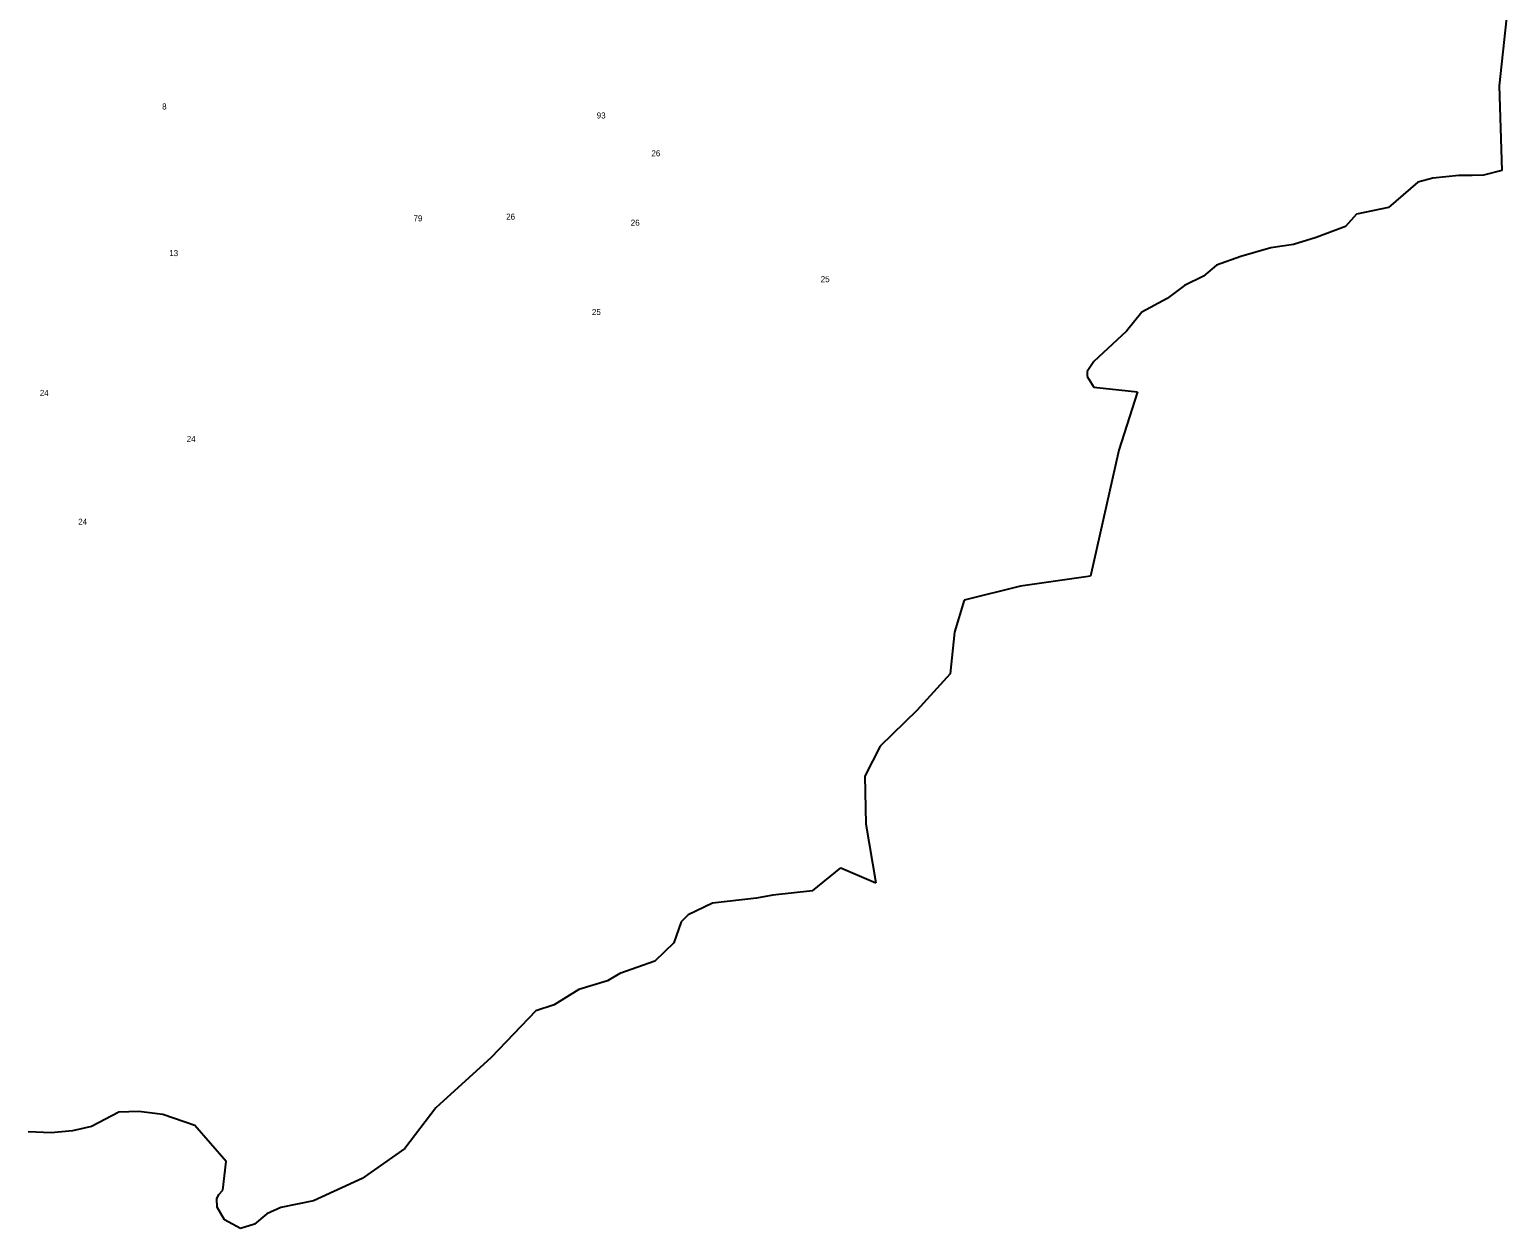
# Model space of a CAD drawing. Extents: x -772472 to -767535, y -969581 to -965387.
# Drawn here: x -770002 to -767535, y -969496 to -967499 of the extents above; entities that cross this region are included whole.
import ezdxf

# ---------------------------------------------------------------- set-up
doc = ezdxf.new("R2010")
doc.units = 0
doc.layers.add('Vrstva 13', color=7, linetype='Continuous')
doc.layers.add('Vrstva 24', color=7, linetype='Continuous')

msp = doc.modelspace()

# ---------------------------------------------------------------- linework, layer by layer
at = {"layer": 'Vrstva 13'}
for p, q in [((-767534.62, -967420.5), (-767553.38, -967593.03)), ((-767553.38, -967593.03), (-767548.64, -967734.13)), ((-767620.41, -967742.16), (-767663.81, -967746.68)), ((-767598.25, -967742.16), (-767620.41, -967742.16)), ((-767579.27, -967741.71), (-767598.25, -967742.16)), ((-767548.64, -967734.13), (-767579.27, -967741.71)), ((-767688.67, -967753.47), (-767737.5, -967795.53)), ((-767663.81, -967746.68), (-767688.67, -967753.47)), ((-767790.85, -967806.38), (-767809.38, -967827.19)), ((-767737.5, -967795.53), (-767790.85, -967806.38)), ((-767809.38, -967827.19), (-767858.21, -967845.73)), ((-767933.71, -967862.47), (-767983.89, -967876.94)), ((-767896.18, -967857.04), (-767933.71, -967862.47)), ((-767858.21, -967845.73), (-767896.18, -967857.04)), ((-767983.89, -967876.94), (-768024.14, -967891.42)), ((-768045.84, -967909.96), (-768077.49, -967925.34)), ((-768024.14, -967891.42), (-768045.84, -967909.96)), ((-768077.49, -967925.34), (-768106.42, -967947.05)), ((-768106.42, -967947.05), (-768148.92, -967969.66)), ((-768148.92, -967969.66), (-768174.23, -968001.32)), ((-768174.23, -968001.32), (-768228.94, -968051.97)), ((-768228.94, -968051.97), (-768239.78, -968068.71)), ((-768239.78, -968068.71), (-768239.78, -968077.3)), ((-768239.78, -968077.3), (-768228.48, -968094.94)), ((-768228.48, -968094.94), (-768156.15, -968102.63)), ((-768156.15, -968102.63), (-768186.89, -968199.87)), ((-768186.89, -968199.87), (-768234.14, -968409.95)), ((-768350.78, -968426.23), (-768444.81, -968449.75)), ((-768234.14, -968409.95), (-768350.78, -968426.23)), ((-768444.81, -968449.75), (-768461.09, -968503.12)), ((-768461.09, -968503.12), (-768468.31, -968572.76)), ((-768468.31, -968572.76), (-768523.47, -968633.37)), ((-768523.47, -968633.37), (-768584.95, -968693.07)), ((-768584.95, -968693.07), (-768610.27, -968742.82)), ((-768610.27, -968742.82), (-768608.46, -968822.42)), ((-768608.46, -968822.42), (-768592.06, -968920.87)), ((-768697.4, -968933.99), (-768650.16, -968895.77)), ((-768650.16, -968895.77), (-768592.06, -968920.87)), ((-768790.87, -968946.08), (-768864.11, -968954.67)), ((-768763.3, -968941.1), (-768790.87, -968946.08)), ((-768697.4, -968933.99), (-768763.3, -968941.1)), ((-768904.35, -968974.12), (-768916.11, -968985.88)), ((-768864.11, -968954.67), (-768904.35, -968974.12)), ((-768916.11, -968985.88), (-768928.76, -969020.7)), ((-768928.76, -969020.7), (-768960.41, -969051.01)), ((-769018.74, -969071.81), (-769039.08, -969084.02)), ((-768960.41, -969051.01), (-769018.74, -969071.81)), ((-769086.55, -969098.49), (-769128.14, -969123.82)), ((-769039.08, -969084.02), (-769086.55, -969098.49)), ((-769128.14, -969123.82), (-769158.43, -969133.77)), ((-769158.43, -969133.77), (-769233.03, -969212.02)), ((-769233.03, -969212.02), (-769325.26, -969295.69)), ((-769325.26, -969295.69), (-769376.8, -969363.53)), ((-769853.3, -969302.92), (-769898.96, -969326.89)), ((-769819.84, -969302.01), (-769853.3, -969302.92)), ((-769780.06, -969306.54), (-769819.84, -969302.01)), ((-769726.72, -969325.08), (-769780.06, -969306.54)), ((-769965.87, -969337.29), (-770004.3, -969335.48)), ((-769930.61, -969334.13), (-769965.87, -969337.29)), ((-769898.96, -969326.89), (-769930.61, -969334.13)), ((-769674.28, -969385.23), (-769726.72, -969325.08)), ((-769376.8, -969363.53), (-769447.77, -969413.28)), ((-769679.7, -969432.72), (-769674.28, -969385.23)), ((-769447.77, -969413.28), (-769528.7, -969450.82)), ((-769690.1, -969447.19), (-769686.48, -969439.96)), ((-769686.48, -969439.96), (-769679.7, -969432.72)), ((-769689.19, -969461.21), (-769690.1, -969447.19)), ((-769676.99, -969482.02), (-769689.19, -969461.21)), ((-769583.4, -969461.66), (-769606.46, -969472.52)), ((-769528.7, -969450.82), (-769583.4, -969461.66)), ((-769650.31, -969496.49), (-769676.99, -969482.02)), ((-769627.26, -969489.25), (-769650.31, -969496.49)), ((-769606.46, -969472.52), (-769627.26, -969489.25))]:
    msp.add_line(p, q, dxfattribs=at)

# ---------------------------------------------------------------- texts
at = {"layer": 'Vrstva 24'}
for s, p in [('8', (-769781.046, -967632.22)), ('93', (-769056.99, -967647.17)), ('26', (-768965.93, -967710.2)), ('79', (-769362.318, -967818.54)), ('26', (-769207.87, -967815.7)), ('26', (-769000.33, -967825.86)), ('13', (-769769.271, -967876.53)), ('25', (-768683.746, -967919.94)), ('25', (-769064.986, -967974.66)), ('24', (-769984.932, -968109.37)), ('24', (-769740.172, -968186.1)), ('24', (-769920.912, -968324.06))]:
    msp.add_text(s, height=10, dxfattribs=at).set_placement(p)

doc.saveas('drawing.dxf')
